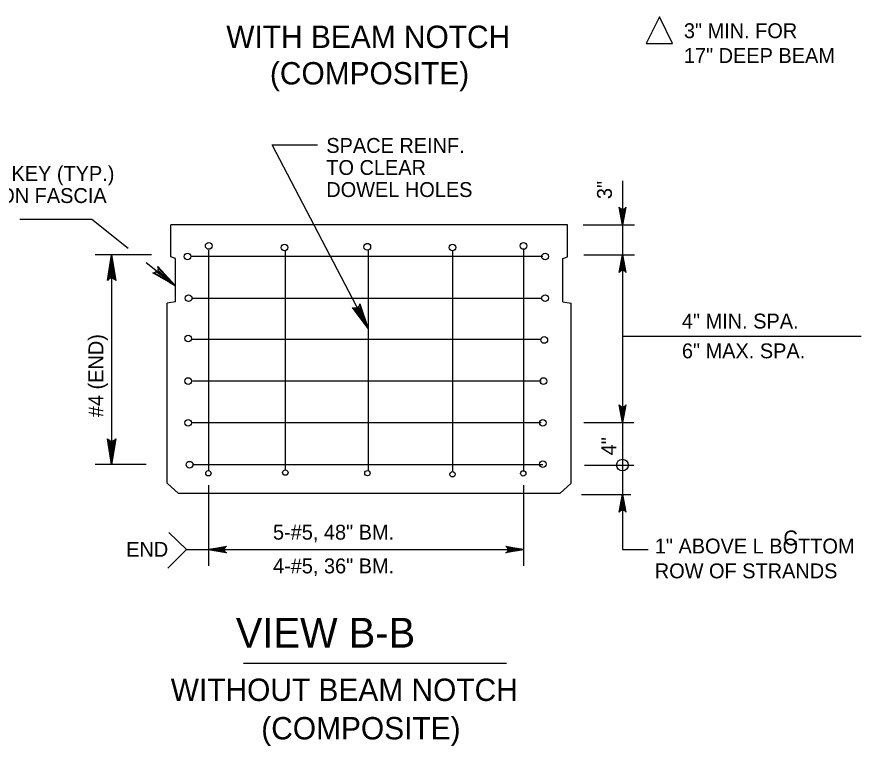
# Model space of a CAD drawing. Extents: x 639331 to 643089, y 299088 to 300975.
# Drawn here: x 640986.5 to 641156.5, y 300579.4 to 300726.3 of the extents above; entities that cross this region are included whole.
import ezdxf

# ---------------------------------------------------------------- set-up
doc = ezdxf.new("R2010")
doc.units = 0
doc.layers.add('1', color=7, linetype='Continuous')

msp = doc.modelspace()

# ---------------------------------------------------------------- linework, layer by layer
at = {"layer": '1'}
for p, q in [((641037.87, 300700.5), (641047, 300700.5)), ((641057.17, 300663.54), (641037.87, 300700.5)), ((641108.44, 300693.26), (641108.44, 300684.09)), ((640987.07, 300685.53), (641001.58, 300685.53)), ((641001.58, 300685.53), (641008.87, 300679.72)), ((641097.31, 300684.39), (641017.48, 300684.39)), ((641017.48, 300677.92), (641017.48, 300684.39)), ((641097.31, 300677.92), (641097.31, 300684.39)), ((641100.47, 300684.39), (641110.84, 300684.39)), ((641108.44, 300684.39), (641108.44, 300678.37)), ((641013.58, 300678.37), (641002.25, 300678.37)), ((641005.55, 300678.37), (641005.55, 300636.13)), ((641018.38, 300677.62), (641017.48, 300677.92)), ((641021.5, 300678.07), (641092.35, 300678.07)), ((641025.08, 300679.28), (641025.08, 300634.92)), ((641040.48, 300679.13), (641040.48, 300635.07)), ((641057.17, 300679.28), (641057.17, 300634.92)), ((641074.16, 300679.13), (641074.16, 300634.77)), ((641088.48, 300679.43), (641088.48, 300634.92)), ((641096.41, 300677.62), (641097.31, 300677.92)), ((641100.62, 300678.37), (641110.84, 300678.37)), ((641108.44, 300678.37), (641108.44, 300644.55)), ((641012.51, 300676.82), (641018.38, 300672.13)), ((641018.38, 300668.9), (641018.38, 300677.62)), ((641096.41, 300668.9), (641096.41, 300677.62)), ((641021.72, 300669.65), (641092.2, 300669.65)), ((641018.38, 300668.9), (641016.72, 300668.6)), ((641016.72, 300632.37), (641016.72, 300668.6)), ((641096.41, 300668.9), (641098.06, 300668.6)), ((641098.06, 300632.37), (641098.06, 300668.6)), ((641021.69, 300661.38), (641092.05, 300661.38)), ((641108.44, 300662), (641156.45, 300662)), ((641021.84, 300652.97), (641092.05, 300652.97)), ((641021.69, 300644.55), (641092.05, 300644.55)), ((641100.62, 300644.55), (641110.69, 300644.55)), ((641108.44, 300644.55), (641108.44, 300635.98)), ((641012.49, 300636.13), (641002.25, 300636.13)), ((641021.84, 300636.13), (641092.35, 300636.13)), ((641100.77, 300635.98), (641110.69, 300635.98)), ((641108.44, 300635.98), (641108.44, 300630.26)), ((641016.72, 300632.37), (641018.98, 300630.26)), ((641025.08, 300631.98), (641025.08, 300615.71)), ((641088.48, 300631.98), (641088.48, 300615.71)), ((641095.81, 300630.26), (641098.06, 300632.37)), ((641095.81, 300630.26), (641018.98, 300630.26)), ((641108.44, 300630.26), (641108.44, 300618.99)), ((641100.17, 300630.11), (641110.09, 300630.11)), ((641020.59, 300618.99), (641017.07, 300622.41)), ((641020.59, 300618.99), (641016.87, 300615.27)), ((641020.59, 300618.99), (641088.48, 300618.99)), ((641108.44, 300618.99), (641113.56, 300618.99)), ((641032.07, 300596.12), (641085.07, 300596.12))]:
    msp.add_line(p, q, dxfattribs=at)
msp.add_lwpolyline([(641113.16, 300720.93), (641118.51, 300720.93), (641115.83, 300726.28)], close=True, dxfattribs=at)
for points in [[(641108.44, 300684.39), (641107.77, 300687.98), (641107.86, 300687.84), (641107.96, 300687.7), (641108.08, 300687.63), (641108.2, 300687.56), (641108.32, 300687.54), (641108.44, 300687.52), (641108.56, 300687.54), (641108.68, 300687.56), (641108.8, 300687.63), (641108.92, 300687.7), (641109.02, 300687.84), (641109.11, 300687.98), (641108.44, 300684.39), (641109.02, 300687.84), (641108.92, 300687.7), (641108.44, 300684.39), (641108.8, 300687.63), (641108.68, 300687.56), (641108.44, 300684.39), (641108.56, 300687.54), (641108.44, 300687.52), (641108.44, 300684.39), (641108.32, 300687.54), (641108.2, 300687.56), (641108.44, 300684.39), (641108.08, 300687.63), (641107.96, 300687.7), (641108.44, 300684.39), (641107.86, 300687.84)], [(641004.93, 300673.46), (641005.29, 300673.64), (641005.55, 300678.37), (641004.93, 300673.46), (641004.71, 300673.21), (641005.55, 300678.37), (641005.78, 300673.65), (641006.13, 300673.47), (641005.55, 300678.37), (641006.37, 300673.21), (641006.13, 300673.47)], [(641108.44, 300678.37), (641109.11, 300674.79), (641109.02, 300674.92), (641108.92, 300675.06), (641108.8, 300675.13), (641108.68, 300675.21), (641108.56, 300675.23), (641108.44, 300675.25), (641108.32, 300675.23), (641108.2, 300675.21), (641108.08, 300675.13), (641107.96, 300675.06), (641107.86, 300674.92), (641107.77, 300674.79), (641108.44, 300678.37), (641107.86, 300674.92), (641107.96, 300675.06), (641108.44, 300678.37), (641108.08, 300675.13), (641108.2, 300675.21), (641108.44, 300678.37), (641108.32, 300675.23), (641108.44, 300675.25), (641108.44, 300678.37), (641108.56, 300675.23), (641108.68, 300675.21), (641108.44, 300678.37), (641108.8, 300675.13), (641108.92, 300675.06), (641108.44, 300678.37), (641109.02, 300674.92)], [(641014.92, 300675.68), (641014.84, 300675.29), (641018.38, 300672.13), (641014.92, 300675.68), (641014.86, 300676.01), (641018.38, 300672.13), (641014.54, 300674.9), (641014.18, 300674.73), (641018.38, 300672.13), (641013.83, 300674.71), (641014.18, 300674.73)], [(641055.43, 300668.18), (641055.2, 300667.85), (641057.17, 300663.54), (641055.43, 300668.18), (641055.51, 300668.5), (641057.17, 300663.54), (641054.77, 300667.62), (641054.37, 300667.61), (641057.17, 300663.54), (641054.04, 300667.73), (641054.37, 300667.61)], [(641108.44, 300644.55), (641107.77, 300648.13), (641107.86, 300648), (641107.96, 300647.86), (641108.08, 300647.79), (641108.2, 300647.71), (641108.32, 300647.69), (641108.44, 300647.67), (641108.56, 300647.69), (641108.68, 300647.71), (641108.8, 300647.79), (641108.92, 300647.86), (641109.02, 300648), (641109.11, 300648.13), (641108.44, 300644.55), (641109.02, 300648), (641108.92, 300647.86), (641108.44, 300644.55), (641108.8, 300647.79), (641108.68, 300647.71), (641108.44, 300644.55), (641108.56, 300647.69), (641108.44, 300647.67), (641108.44, 300644.55), (641108.32, 300647.69), (641108.2, 300647.71), (641108.44, 300644.55), (641108.08, 300647.79), (641107.96, 300647.86), (641108.44, 300644.55), (641107.86, 300648)], [(641006.16, 300641.04), (641005.81, 300640.86), (641005.55, 300636.13), (641006.16, 300641.04), (641006.38, 300641.29), (641005.55, 300636.13), (641005.31, 300640.85), (641004.96, 300641.03), (641005.55, 300636.13), (641004.73, 300641.29), (641004.96, 300641.03)], [(641108.44, 300630.11), (641109.11, 300626.52), (641109.02, 300626.66), (641108.92, 300626.8), (641108.8, 300626.87), (641108.68, 300626.94), (641108.56, 300626.96), (641108.44, 300626.98), (641108.32, 300626.96), (641108.2, 300626.94), (641108.08, 300626.87), (641107.96, 300626.8), (641107.86, 300626.66), (641107.77, 300626.52), (641108.44, 300630.11), (641107.86, 300626.66), (641107.96, 300626.8), (641108.44, 300630.11), (641108.08, 300626.87), (641108.2, 300626.94), (641108.44, 300630.11), (641108.32, 300626.96), (641108.44, 300626.98), (641108.44, 300630.11), (641108.56, 300626.96), (641108.68, 300626.94), (641108.44, 300630.11), (641108.8, 300626.87), (641108.92, 300626.8), (641108.44, 300630.11), (641109.02, 300626.66)], [(641025.08, 300618.99), (641028.67, 300619.66), (641028.53, 300619.56), (641028.39, 300619.47), (641028.32, 300619.35), (641028.25, 300619.23), (641028.23, 300619.11), (641028.21, 300618.99), (641028.23, 300618.87), (641028.25, 300618.75), (641028.32, 300618.63), (641028.39, 300618.5), (641028.53, 300618.41), (641028.67, 300618.31), (641025.08, 300618.99), (641028.53, 300618.41), (641028.39, 300618.5), (641025.08, 300618.99), (641028.32, 300618.63), (641028.25, 300618.75), (641025.08, 300618.99), (641028.23, 300618.87), (641028.21, 300618.99), (641025.08, 300618.99), (641028.23, 300619.11), (641028.25, 300619.23), (641025.08, 300618.99), (641028.32, 300619.35), (641028.39, 300619.47), (641025.08, 300618.99), (641028.53, 300619.56)], [(641088.48, 300618.99), (641084.89, 300618.31), (641085.03, 300618.41), (641085.16, 300618.5), (641085.24, 300618.63), (641085.31, 300618.75), (641085.33, 300618.87), (641085.35, 300618.99), (641085.33, 300619.11), (641085.31, 300619.23), (641085.24, 300619.35), (641085.16, 300619.47), (641085.03, 300619.56), (641084.89, 300619.66), (641088.48, 300618.99), (641085.03, 300619.56), (641085.16, 300619.47), (641088.48, 300618.99), (641085.24, 300619.35), (641085.31, 300619.23), (641088.48, 300618.99), (641085.33, 300619.11), (641085.35, 300618.99), (641088.48, 300618.99), (641085.33, 300618.87), (641085.31, 300618.75), (641088.48, 300618.99), (641085.24, 300618.63), (641085.16, 300618.5), (641088.48, 300618.99), (641085.03, 300618.41)]]:
    msp.add_lwpolyline(points, dxfattribs=at)
for centre, radius in [((641025.09, 300680.14), 0.672), ((641040.34, 300679.84), 0.672), ((641057.03, 300679.99), 0.672), ((641074.17, 300679.84), 0.672), ((641088.49, 300680.14), 0.672), ((641020.83, 300678.03), 0.672), ((641092.81, 300678.03), 0.672), ((641021.05, 300669.62), 0.672), ((641092.81, 300669.62), 0.672), ((641020.95, 300661.5), 0.672), ((641092.66, 300661.2), 0.672), ((641020.95, 300652.93), 0.672), ((641092.51, 300652.93), 0.672), ((641020.95, 300644.51), 0.672), ((641092.36, 300644.51), 0.672), ((641108.39, 300636), 1.18), ((641021.25, 300636.09), 0.672), ((641092.36, 300636.18), 0.672), ((641025.02, 300634.36), 0.538), ((641040.52, 300634.49), 0.538), ((641057.05, 300634.38), 0.538), ((641074.18, 300634.15), 0.538), ((641088.43, 300634.33), 0.538)]:
    msp.add_circle(centre, radius, dxfattribs=at)

# ---------------------------------------------------------------- texts
for s, height, p in [('WITH BEAM NOTCH', 4.5, (641028.63, 300720.02)), ('3" MIN. FOR', 3, (641120.77, 300721.99)), ('17" DEEP BEAM', 3, (641120.77, 300716.99)), ('(COMPOSITE)', 4.5, (641037.42, 300712.67)), ('SPACE REINF.', 3, (641048.77, 300698.88)), ('TO CLEAR', 3, (641048.77, 300694.44)), ('SHEAR KEY (TYP.)', 3, (640970.44, 300693.24)), ('(OMIT ON FASCIA', 3, (640970.44, 300688.79)), ('DOWEL HOLES', 3, (641048.77, 300690)), ('4" MIN. SPA.', 3, (641120.37, 300663.51)), ('6" MAX. SPA.', 3, (641120.37, 300657.51)), ('5-#5, 48" BM.', 3, (641038.03, 300620.99)), ('C', 3, (641140.82, 300619.84)), ('END', 3, (641008.47, 300617.54)), ('1" ABOVE L BOTTOM', 3, (641114.91, 300618.2)), ('4-#5, 36" BM.', 3, (641038.04, 300614.2)), ('ROW OF STRANDS', 3, (641114.91, 300613.2)), (' VIEW B-B', 6, (641028.32, 300599.24)), ('WITHOUT BEAM NOTCH', 4.5, (641017.45, 300588.5)), ('(COMPOSITE)', 4.5, (641035.68, 300580.76))]:
    msp.add_text(s, height=height, dxfattribs=at).set_placement(p)
for s, p in [('3"', (641106.28, 300689.58)), ('#4 (END)', (641003.88, 300645.66)), ('4"', (641107.14, 300637.97))]:
    msp.add_text(s, height=3, rotation=90, dxfattribs=at).set_placement(p)

doc.saveas('drawing.dxf')
